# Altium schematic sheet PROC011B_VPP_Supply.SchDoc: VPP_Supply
size 431 x 279 mm; Date: Not shown in title block; ApprovedBy: Not shown in title block; CheckedBy: Not shown in title block; Author: Not shown in title block; CompanyName: Not shown in title block; Engineer: Not shown in title block; Organization: Not shown in title block; Address1: Not shown in title block; Address2: Not shown in title block; Address3: Not shown in title block; Address4: Not shown in title block; DocumentNumber: 1; Revision: Use project parameter SCH_Rev; SheetNumber: 6; SheetTotal: 17; PageSetup: Record=PageOptions¦CenterHorizontal=True¦CenterVertical=True¦PrintScale=1.00¦XCorrection=1.00¦YCorrection=1.00¦PrintKind=0¦BorderSize=5000000¦LeftOffset=0¦BottomOffset=0¦Orientation=2¦PaperLength=1000¦PaperWidth=1000¦Scale=100¦PaperSource=15¦PrintQuality=600¦MediaType=1¦DitherType=10¦PaperKind=Letter¦PrintScaleMode=1
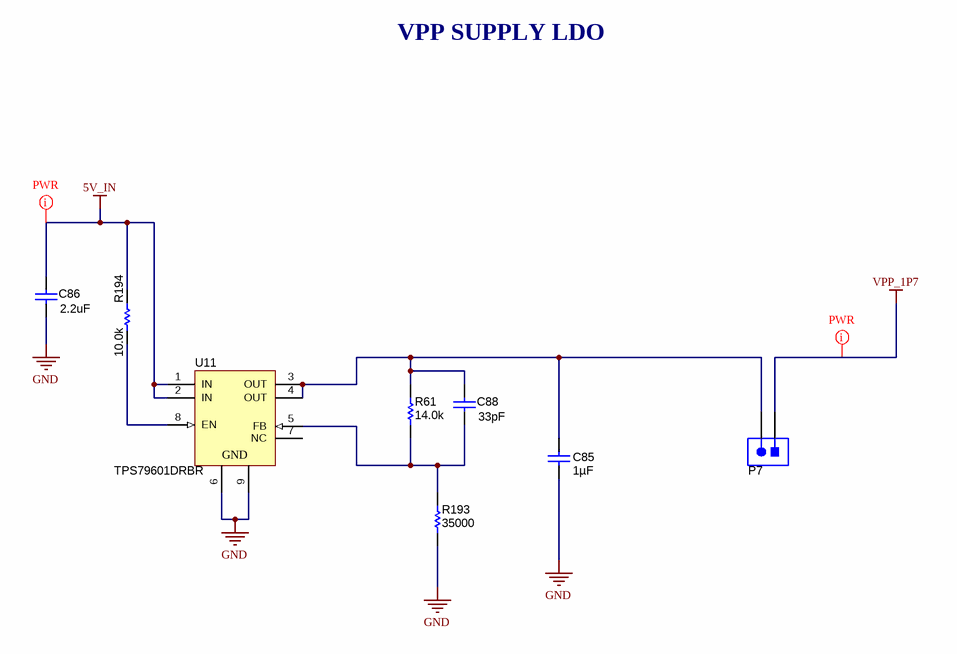
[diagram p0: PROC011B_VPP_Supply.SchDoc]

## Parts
C85  ValueDisplayed: 1µF  [0402L]  (hidden comment: C1005X7S0J105M050BC)
C86  ValueDisplayed: 2.2uF  [0402_065L]  (hidden comment: C1005X7S1A225K050BC)
C88  ValueDisplayed: 33pF  [0402L]  (hidden comment: C0402C330J5GAC)
P7  TSW-102-07-G-S  [TSW-102-07-X-S]  (value not drawn)
R61  ValueDisplayed: 14.0k  [0402L]  (hidden comment: CRCW040214K0FKED)
R193  ValueDisplayed: 35000  [0402L]  (hidden comment: PNM0402E3502BST1)
R194  ValueDisplayed: 10.0k  [0402L]  (hidden comment: CRCW040210K0FKED)
U11  TPS79601DRBR  [DRB0008B]

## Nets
5V_IN: C86.2 R194.1 U11.1(IN) U11.2(IN)
GND: C85.1 C86.1 R193.1 U11.6(GND) U11.9(GND)
VPP_1P7: P7.1
NetC85_2: C85.2 C88.1 P7.2 R61.2 U11.3(OUT) U11.4(OUT)
NetC88_2: C88.2 R61.1 R193.2 U11.5(FB)
NetR194_2: R194.2 U11.8(EN)

Not connected (* = marked no-connect by the designer): U11 7(NC)

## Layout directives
net class PWR: 5V_IN, VPP_1P7

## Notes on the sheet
- VPP SUPPLY LDO

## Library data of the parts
C85 = CMP-0078222-1: CAP, CERM, 1 µF, 6.3 V,+/- 20%, X7S, 0402; Manufacturer: TDK; TaMin_C: -55°C; Polarized: N; SizeAreaWB_mm2: 3; U/M: EA; Value: 1uF; TaMax_C: 125°C; SizeZ_mm: 0.6; SizeX_mm: 1; SizeY_mm: 0.5; Cap_Case: 0402; Value2: 6.3V; AEC Category: Q200
C86 = CMP-0006302-2: CAP, CERM, 2.2 uF, 10 V, +/- 10%, X7S, 0402; Manufacturer: TDK; TaMin_C: -55°C; ESR_ohm: 5.925m; Polarized: N; SizeAreaWB_mm2: 3; Value1: 0.005925 ohm; U/M: EA; Value: 2.2uF; TaMax_C: 125°C; SizeZ_mm: 0.65; SizeX_mm: 1; SizeY_mm: 0.5; Cap_Case: 0402_065; Value2: 10V; CompType: Capacitor; Cap_F: 2.2µF; IRMS_A: 2.05591A; AEC Category: Q200
C88 = CMP-0006242-2: CAP, CERM, 33 pF, 50 V, +/- 5%, C0G/NP0, 0402; Manufacturer: Kemet; TaMin_C: -55°C; Polarized: N; SizeAreaWB_mm2: 3; Value1: Unknown; U/M: EA; Value: 33pF; TaMax_C: 125°C; SizeZ_mm: 0.6; SizeX_mm: 1; SizeY_mm: 0.5; Cap_Case: 0402; Value2: 50V; AEC Category: Q200
P7 = CMP-0075405-1: Header, 100mil, 2x1, Gold, TH; Manufacturer: Samtec; Pitch_mm: 2.54; Cert_VDE: N; Gender: Male; Cert_CSA: Y; Voltage_V: 550V; Green_REACh: Passed; Current_A: 6.3A; CT: False; Green_Lifecycle: Active; Row_Count: 1; CNHeader: True
R61 = CMP-0026015-2: RES, 14.0 k, 1%, 0.063 W, 0402; Manufacturer: Vishay-Dale; Power_W: 63mW; TempCo: 100 ppm/C; Value_Code: 14k0; U/M: EA; Value: 14.0k; EIA_Code: E96; Res_ohm: 14k; SizeX_mm: 1; SizeY_mm: 0.5; SizeZ_mm: 0.6; Value2: 0.063W; VDC_V: 50V; AEC Category: Q200
R193 = CMP-0078213-1: RES, 35000, 0.1%, 0.05 W, 0402; Manufacturer: Vishay-Dale; Value_Code: 35k0; SizeArea_mm2: 0.5; AEC Qualified: N; AEC Category: Q200; Res_ohm: 35k; Value: 35.0k; SizeZ_mm: 0.6; TempCo: 25 ppm/C; Power_W: 50mW; VDC_V: 75V; Value2: 0.05W; U/M: EA; SizeX_mm: 1
R194 = CMP-0025958-2: RES, 10.0 k, 1%, 0.063 W, 0402; Manufacturer: Vishay-Dale; Power_W: 63mW; TempCo: 100 ppm/C; Value_Code: 10k0; U/M: EA; Value: 10.0k; EIA_Code: E96; Res_ohm: 10k; SizeX_mm: 1; SizeY_mm: 0.5; SizeZ_mm: 0.6; Value2: 0.063W; VDC_V: 50V; AEC Category: Q200
U11 = CMP-0036402-2: Single Output High PSRR LDO, 1 A, Adjustable 1.2 to 5.5 V Output, 2.7 to 5.5 V Input, 8-pin SON (DRB), -40 to 125 degC, Green (RoHS & no Sb/Br); Manufacturer: Texas Instruments; Vin(Min)(V): 2.7; Vout Adj(Max)(V): 5.5; Vout Adj(Min)(V): 1.2; Accuracy(%): 2; SubFamily: Single Channel LDO; Iq(Typ)(mA): 0.26; Vdo(Typ)(mV): 250; Iout(Max)(A): 1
